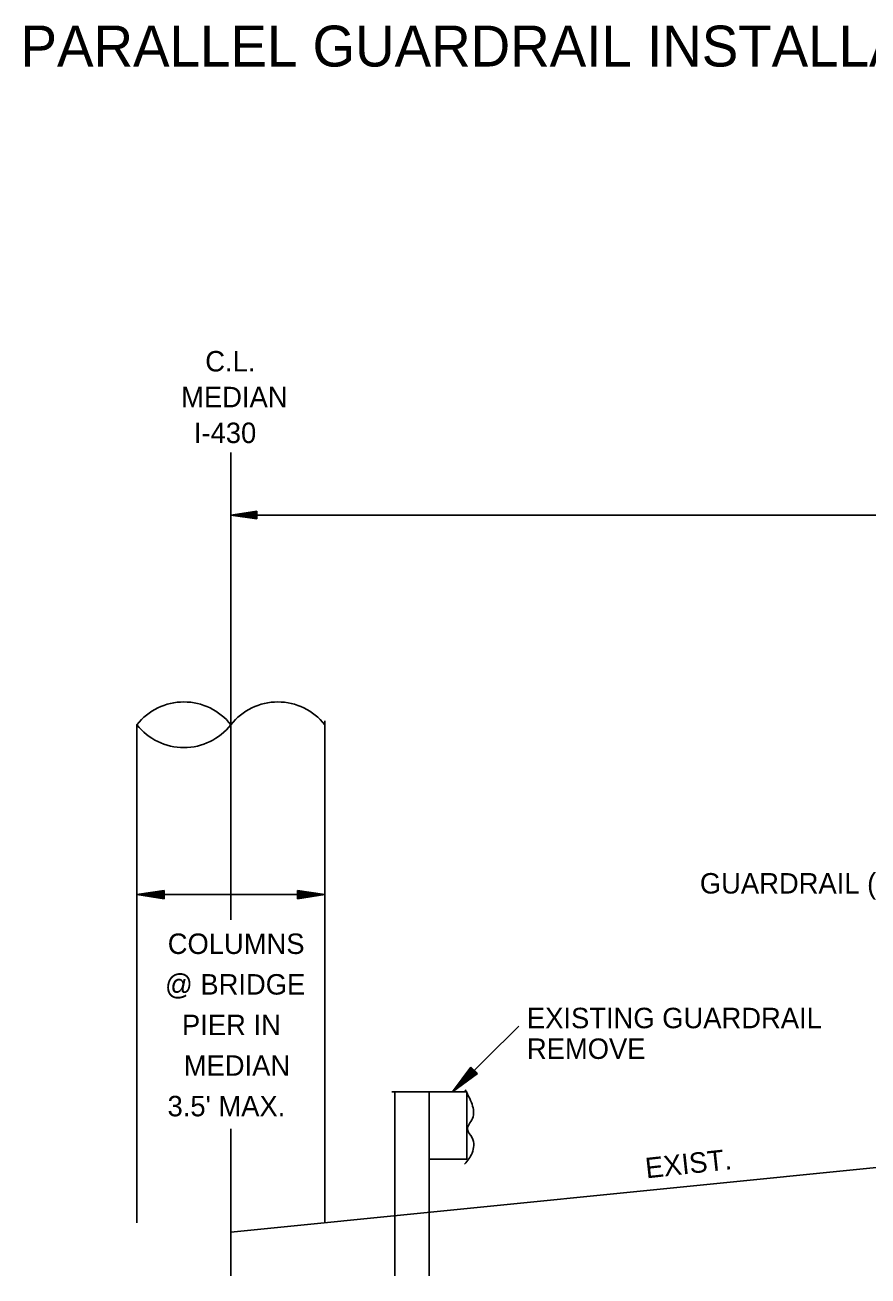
# Model space of a CAD drawing. Extents: x 1373853 to 1374003, y 380191 to 380927.
# Drawn here: x 1373897.08 to 1373921.8, y 380363.43 to 380400.12 of the extents above; entities that cross this region are included whole.
import ezdxf

# ---------------------------------------------------------------- set-up
doc = ezdxf.new("R2010")
doc.units = 0
doc.layers.add('Default', color=7, linetype='Continuous')
doc.layers.add('R_Border Notes', color=7, linetype='Continuous')

msp = doc.modelspace()

# ---------------------------------------------------------------- linework, layer by layer
at = {"layer": 'Default'}
for p, q in [((1373903.117, 380373.874), (1373903.117, 380387.58)), ((1373903.879, 380385.859), (1373903.117, 380385.744)), ((1373948.117, 380385.744), (1373903.117, 380385.744)), ((1373903.879, 380385.63), (1373903.117, 380385.744)), ((1373903.879, 380385.84), (1373903.246, 380385.744)), ((1373903.879, 380385.649), (1373903.246, 380385.744)), ((1373903.879, 380385.82), (1373903.377, 380385.744)), ((1373903.879, 380385.669), (1373903.377, 380385.744)), ((1373903.879, 380385.802), (1373903.504, 380385.744)), ((1373903.879, 380385.687), (1373903.504, 380385.744)), ((1373903.879, 380385.783), (1373903.632, 380385.744)), ((1373903.879, 380385.708), (1373903.632, 380385.744)), ((1373903.879, 380385.762), (1373903.759, 380385.744)), ((1373903.879, 380385.727), (1373903.759, 380385.744)), ((1373903.879, 380385.859), (1373903.879, 380385.63)), ((1373900.363, 380364.988), (1373900.363, 380379.594)), ((1373905.872, 380364.988), (1373905.872, 380379.712)), ((1373901.162, 380374.733), (1373900.363, 380374.612)), ((1373901.162, 380374.713), (1373900.498, 380374.612)), ((1373901.162, 380374.692), (1373900.635, 380374.612)), ((1373901.162, 380374.673), (1373900.769, 380374.612)), ((1373901.162, 380374.653), (1373900.903, 380374.612)), ((1373901.162, 380374.631), (1373901.037, 380374.612)), ((1373901.162, 380374.733), (1373901.162, 380374.492)), ((1373905.072, 380374.731), (1373905.872, 380374.612)), ((1373905.072, 380374.491), (1373905.072, 380374.731)), ((1373905.072, 380374.709), (1373905.738, 380374.612)), ((1373905.072, 380374.689), (1373905.6, 380374.612)), ((1373905.072, 380374.67), (1373905.466, 380374.612)), ((1373905.072, 380374.65), (1373905.332, 380374.612)), ((1373905.072, 380374.629), (1373905.197, 380374.612)), ((1373905.872, 380374.612), (1373900.363, 380374.612)), ((1373901.162, 380374.492), (1373900.363, 380374.612)), ((1373901.162, 380374.513), (1373900.498, 380374.612)), ((1373901.162, 380374.533), (1373900.635, 380374.612)), ((1373901.162, 380374.552), (1373900.769, 380374.612)), ((1373901.162, 380374.574), (1373900.903, 380374.612)), ((1373901.162, 380374.595), (1373901.037, 380374.612)), ((1373905.072, 380374.491), (1373905.872, 380374.612)), ((1373905.072, 380374.571), (1373905.332, 380374.612)), ((1373905.072, 380374.532), (1373905.6, 380374.612)), ((1373905.072, 380374.511), (1373905.738, 380374.612)), ((1373905.072, 380374.55), (1373905.466, 380374.612)), ((1373905.072, 380374.593), (1373905.197, 380374.612)), ((1373911.558, 380370.755), (1373909.614, 380368.828)), ((1373910.158, 380369.557), (1373909.614, 380368.828)), ((1373910.174, 380369.541), (1373909.721, 380368.933)), ((1373910.19, 380369.525), (1373909.831, 380369.042)), ((1373910.206, 380369.509), (1373909.937, 380369.148)), ((1373910.222, 380369.492), (1373910.045, 380369.255)), ((1373910.348, 380369.365), (1373910.158, 380369.557)), ((1373910.348, 380369.365), (1373909.614, 380368.828)), ((1373910.332, 380369.381), (1373909.721, 380368.933)), ((1373910.316, 380369.398), (1373909.831, 380369.042)), ((1373910.3, 380369.414), (1373909.937, 380369.148)), ((1373910.284, 380369.43), (1373910.045, 380369.255)), ((1373910.238, 380369.476), (1373910.152, 380369.361)), ((1373910.268, 380369.446), (1373910.152, 380369.361)), ((1373910.036, 380368.828), (1373907.834, 380368.828)), ((1373907.921, 380368.819), (1373907.921, 380363.428)), ((1373908.935, 380368.828), (1373908.935, 380363.428)), ((1373910.036, 380368.828), (1373910.036, 380366.858)), ((1373903.117, 380363.428), (1373903.117, 380367.741)), ((1373910.036, 380366.858), (1373908.935, 380366.858))]:
    msp.add_line(p, q, dxfattribs=at)
for centre, start, end in [((1373901.74, 380378.515), 38.0711, 141.9289), ((1373904.495, 380378.515), 38.0711, 141.9289), ((1373901.74, 380380.673), 218.0711, 321.9289)]:
    msp.add_arc(centre, 1.749, start, end, dxfattribs=at)
msp.add_spline([(1373909.984, 380368.891), (1373910.191, 380368.463), (1373910.201, 380368.048), (1373910.053, 380367.725), (1373910.191, 380367.482), (1373910.191, 380367.034), (1373909.972, 380366.71)], degree=3, dxfattribs=at)
at = {"layer": 'R_Border Notes'}
msp.add_line((1373939.117, 380368.313), (1373903.117, 380364.713), dxfattribs=at)

# ---------------------------------------------------------------- texts
at = {"layer": 'Default'}
for s, height, rotation, p in [('PARALLEL GUARDRAIL INSTALLATION FOR MEDIAN BRIDGE PIERS', 1.2, 359.9999, (1373896.95, 380398.899)), ('EXIST.', 0.6, 6.1874, (1373915.303, 380366.289))]:
    msp.add_text(s, height=height, rotation=rotation, dxfattribs=at).set_placement(p)
for s, p in [('C.L.', (1373902.366, 380389.956)), ('MEDIAN', (1373901.66, 380388.906)), ('I-430', (1373902.033, 380387.856)), ('GUARDRAIL (TYPE A)', (1373916.871, 380374.644)), ('COLUMNS', (1373901.266, 380372.872)), ('@ BRIDGE', (1373901.186, 380371.681)), ('PIER IN', (1373901.684, 380370.491)), ('EXISTING GUARDRAIL', (1373911.799, 380370.694)), ('REMOVE', (1373911.799, 380369.794)), ('MEDIAN', (1373901.736, 380369.301)), ("3.5' MAX.", (1373901.261, 380368.111))]:
    msp.add_text(s, height=0.6, dxfattribs=at).set_placement(p)

doc.saveas('drawing.dxf')
